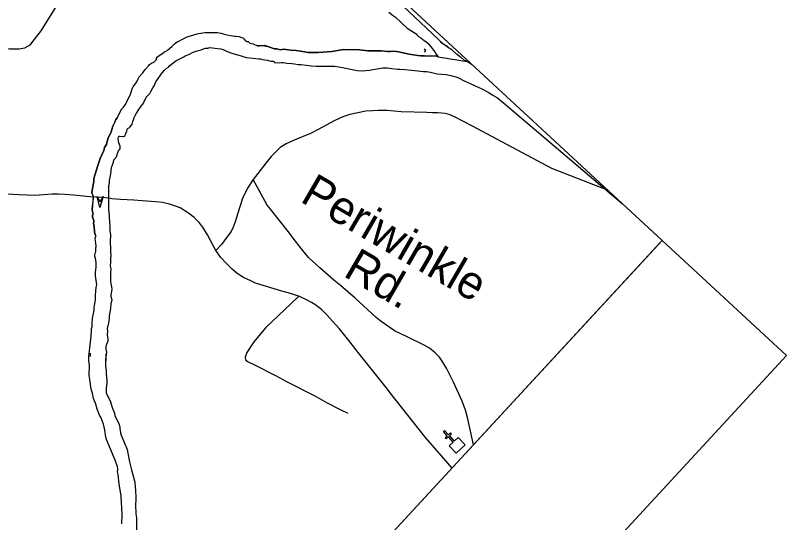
# Model space of a CAD drawing. Extents: x 1766669 to 1770980, y 998119 to 1002502.
# Drawn here: x 1767473.1 to 1767826.5, y 999768 to 1000000.2 of the extents above; entities that cross this region are included whole.
import ezdxf

# ---------------------------------------------------------------- set-up
doc = ezdxf.new("R2010")
doc.units = 0
for name, color, linetype in [('Default', 7, 'Continuous'), ('Default Symbol CELL', 7, 'Continuous'), ('Exist DTM Breakline', 7, 'Continuous'), ('Exist DTM Breakline Underwater', 7, 'Continuous'), ('Exist Roads EOP Other', 7, 'Continuous'), ('Exist Roads EOT', 7, 'Continuous'), ('Exist Structure Minor Paved Ditch or Gutter', 7, 'Continuous'), ('Exist Structure Minor Pipes RCP 24 Inch', 7, 'Continuous')]:
    doc.layers.add(name, color=color, linetype=linetype)

msp = doc.modelspace()

# ---------------------------------------------------------------- linework, layer by layer
at = {"layer": 'Default'}
msp.add_lwpolyline([(1766911.45, 999825.82), (1767342.39, 1000292.03), (1767769.56, 999897.17), (1767338.62, 999430.96)], close=True, dxfattribs=at)
at = {"layer": 'Default Symbol CELL'}
for p, q in [((1767342.36, 1000292.01), (1767826.53, 999844.47)), ((1767768.82, 999896.41), (1767338.6, 999430.98)), ((1767826.53, 999844.47), (1767395.61, 999378.28))]:
    msp.add_line(p, q, dxfattribs=at)
at = {"layer": 'Exist DTM Breakline'}
msp.add_line((1767673.22, 999792.94), (1767668.44, 999798.57), dxfattribs=at)
for points in [[(1767744.52, 999920.27), (1767718.97, 999930.12), (1767682.53, 999949.56), (1767674.38, 999953.84), (1767671.91, 999954.85), (1767670.13, 999955.34), (1767666.77, 999955.68), (1767664.27, 999955.67), (1767661.59, 999955.83), (1767649.9, 999956.09), (1767643.55, 999956.64), (1767639.34, 999956.7), (1767636.75, 999956.49), (1767633.63, 999956.41), (1767626.44, 999954.8), (1767623.18, 999953.73), (1767619.45, 999952.16), (1767611.78, 999947.92), (1767608.37, 999946.17), (1767600.91, 999943.15), (1767597.25, 999941.41), (1767594.43, 999939.8), (1767590.33, 999935.59), (1767587.91, 999932.55), (1767582.1, 999925.03)], [(1767582.1, 999925.03), (1767579.47, 999921.05), (1767577, 999916.04), (1767576.42, 999913.95), (1767575.64, 999911.71), (1767573.83, 999905.78), (1767572.93, 999903.2), (1767572.01, 999901.34), (1767569.96, 999898.67), (1767567.5, 999895.4), (1767565, 999892.58)], [(1767683.03, 999803.6), (1767680.49, 999815.42), (1767679.34, 999819.47), (1767677.87, 999823.57), (1767673.86, 999832.24), (1767670.79, 999838.35), (1767668.97, 999841.51), (1767667.42, 999843.74), (1767665.42, 999845.79), (1767662.85, 999847.84), (1767660.38, 999849.18), (1767652.71, 999853.09), (1767646.85, 999855.81), (1767644.66, 999857.29), (1767640.75, 999860.09), (1767638.38, 999861.96), (1767628.75, 999870.69), (1767622.06, 999876.52), (1767618.98, 999878.95), (1767612.69, 999884.63), (1767607.44, 999889.36), (1767604.86, 999892.56), (1767601.42, 999896.91), (1767597.59, 999901.84), (1767589.94, 999911.55), (1767588.52, 999913.33), (1767582.1, 999925.03)], [(1767512.56, 999916.78), (1767507.18, 999917.1), (1767502.85, 999917.55), (1767499.63, 999917.94), (1767495.74, 999918.17), (1767492.81, 999918.36), (1767489.89, 999918.34), (1767482.03, 999917.75), (1767474.65, 999918.11), (1767466.43, 999918.58), (1767458.13, 999919.31), (1767453.55, 999919.51), (1767447.21, 999920.15), (1767443.86, 999920.35), (1767440.57, 999920.8)], [(1767565, 999892.58), (1767561.12, 999899.82), (1767559.03, 999903.23), (1767557.28, 999905.34), (1767554.98, 999907.66), (1767552.49, 999909.67), (1767548.55, 999912.06), (1767546.41, 999912.95), (1767543.7, 999913.87), (1767540.54, 999914.57), (1767537.3, 999914.87), (1767531.15, 999915.27), (1767527.31, 999915.56), (1767521.19, 999916.01), (1767517.22, 999916.27), (1767516.11, 999916.51), (1767512.56, 999916.78)], [(1767603.06, 999871.72), (1767598.17, 999873.27), (1767595.23, 999874.03), (1767583.06, 999877.69), (1767580.92, 999878.68), (1767577.64, 999880.27), (1767574.78, 999882.03), (1767572.42, 999883.99), (1767569.83, 999886.59), (1767567.25, 999889.4), (1767565, 999892.58)], [(1767603.06, 999871.72), (1767599.34, 999868.17), (1767587.83, 999857.28), (1767582.39, 999850.7), (1767579.2, 999845.85), (1767578.36, 999843.81), (1767578.58, 999842.56), (1767579.75, 999841.63), (1767582.68, 999840.25), (1767592.29, 999835.4), (1767597.31, 999832.59), (1767610.39, 999826.04), (1767615.61, 999823.05), (1767621.87, 999819.79), (1767625.41, 999818.07)], [(1767668.44, 999798.57), (1767661.05, 999807.01), (1767644.88, 999827.47), (1767643.59, 999829.08), (1767630.21, 999845.9), (1767626.54, 999850.67), (1767621.61, 999856.73), (1767618.46, 999860.28), (1767615.82, 999863.13), (1767613.32, 999865.49), (1767610.76, 999867.55), (1767608.77, 999868.83), (1767606.8, 999869.87), (1767603.06, 999871.72)]]:
    msp.add_lwpolyline(points, dxfattribs=at)
at = {"layer": 'Exist DTM Breakline Underwater'}
msp.add_lwpolyline([(1767546.9, 1000094.09), (1767543.97, 1000089.39), (1767543.53, 1000088.68), (1767539.35, 1000082.48), (1767527.82, 1000062.47), (1767521.46, 1000052.31), (1767512.44, 1000038.59), (1767508.74, 1000032.63), (1767496.39, 1000011.99), (1767484.78, 999993.13), (1767480.48, 999987.65), (1767479.64, 999986.62), (1767477.21, 999985.17), (1767474.96, 999984.72), (1767470.32, 999984.72), (1767464.69, 999985.28), (1767456.33, 999986.13), (1767449.03, 999986.62)], dxfattribs=at)
at = {"layer": 'Exist Roads EOP Other'}
msp.add_lwpolyline([(1767513.34, 999917.27), (1767511.8, 999912.26), (1767510.63, 999917.37), (1767511.9, 999914.88)], close=True, dxfattribs=at)
at = {"layer": 'Exist Roads EOT'}
for p, q in [((1767668.65, 999987.39), (1767667.88, 999987.99)), ((1767671.3, 999985.83), (1767668.65, 999987.39)), ((1767661.18, 999984.11), (1767660.41, 999984.84)), ((1767660.56, 999983.46), (1767661.18, 999984.11)), ((1767507.45, 999844.03), (1767507.46, 999845.56)), ((1767514.69, 999842.02), (1767514.72, 999845.29))]:
    msp.add_line(p, q, dxfattribs=at)
for points in [[(1767682.65, 999977.5), (1767681.68, 999978.04), (1767680.07, 999979.11), (1767678.93, 999979.59), (1767677.27, 999981.05), (1767676.73, 999981.33), (1767675.56, 999982.3), (1767675.25, 999982.45), (1767673.06, 999984.48), (1767671.14, 999985.66), (1767670.32, 999986.27), (1767669.51, 999986.93), (1767525.88, 1000122.37)], [(1767644.19, 1000001.69), (1767646.32, 1000000.07), (1767647.25, 999999.47), (1767652.69, 999994.43), (1767656.24, 999992.11), (1767656.71, 999991.73), (1767657.18, 999991.19), (1767657.81, 999990.62), (1767658.93, 999989.99), (1767660.46, 999988.68), (1767661.18, 999988.25), (1767662.39, 999987.16), (1767665.35, 999983.6), (1767665.87, 999982.54), (1767666.83, 999981.22), (1767665.55, 999981.68)], [(1767541.76, 999983.76), (1767542.45, 999984.09), (1767542.79, 999984.27), (1767544.77, 999985.95), (1767545.48, 999986.81), (1767545.97, 999987.23), (1767546.54, 999987.53), (1767547.43, 999988.24), (1767547.95, 999988.44), (1767549.65, 999989.33), (1767551.82, 999990.36), (1767556.45, 999991.85), (1767558.87, 999992.25), (1767560.13, 999992.39), (1767561.36, 999992.44), (1767563.76, 999992.46), (1767565.65, 999992.34), (1767567.37, 999992.06), (1767568.76, 999991.65), (1767571.58, 999991.01), (1767573.72, 999990.79), (1767574.33, 999990.7)], [(1767574.33, 999990.7), (1767575.53, 999990.52), (1767576.73, 999990.19), (1767577.31, 999989.93), (1767577.82, 999989.54), (1767578.55, 999988.64), (1767578.83, 999988.45), (1767579.16, 999988.29), (1767579.71, 999988.24), (1767580.51, 999987.6), (1767582.07, 999987.28), (1767584.02, 999986.36)], [(1767665.55, 999981.68), (1767663.87, 999981.64), (1767660.61, 999981.68), (1767658.96, 999981.73), (1767657.54, 999981.92), (1767653.49, 999982.55), (1767648.74, 999983.56), (1767646.79, 999983.82), (1767644.99, 999983.74), (1767643.63, 999983.77), (1767640.79, 999983.97), (1767638.3, 999983.94), (1767634.67, 999984.09), (1767630.74, 999984.51), (1767623.46, 999984.56), (1767618.05, 999983.77), (1767611.92, 999983.32), (1767607.2, 999983.28), (1767604.62, 999983.74), (1767603.71, 999983.81), (1767601.71, 999984.14), (1767599.37, 999984.36), (1767597.03, 999984.7), (1767595.86, 999984.74), (1767594.9, 999984.54), (1767594.04, 999984.58), (1767592.87, 999984.91), (1767592.4, 999984.86), (1767591.84, 999984.93), (1767588.84, 999986.06), (1767588.38, 999986.17), (1767587.72, 999986.22), (1767587.18, 999986.4), (1767584.84, 999986.3), (1767584.02, 999986.36)], [(1767515.76, 999921.57), (1767515.96, 999922.08), (1767516.13, 999922.83), (1767516.19, 999923.63), (1767516.16, 999924.63), (1767516.87, 999927.68), (1767517.21, 999930.63), (1767517.98, 999933), (1767518.17, 999934.03), (1767519.46, 999935.44), (1767520.19, 999937.85), (1767520.54, 999938.62), (1767520.94, 999939.02), (1767521.13, 999939.48), (1767521.15, 999940.04), (1767521.09, 999940.36), (1767520.87, 999941.14), (1767520.54, 999941.87), (1767520.33, 999942.66), (1767520.24, 999943.91), (1767520.27, 999944.44), (1767520.36, 999944.65), (1767520.57, 999944.89), (1767521.02, 999945), (1767522.12, 999944.74), (1767522.53, 999944.77), (1767522.9, 999944.89), (1767523.38, 999945.3), (1767523.55, 999945.88), (1767524.22, 999947.19), (1767524.35, 999948.08), (1767524.73, 999948.54), (1767525.16, 999948.76), (1767525.53, 999949.07), (1767526.26, 999949.97), (1767526.53, 999950.47), (1767526.87, 999951.66), (1767527.19, 999952.35), (1767527.59, 999953.54), (1767527.96, 999954.33), (1767528.61, 999955.52), (1767528.96, 999955.96), (1767529.34, 999956.67), (1767531.06, 999959.15), (1767531.41, 999959.5), (1767531.88, 999960.18), (1767532.04, 999960.83), (1767532.53, 999961.65), (1767532.96, 999962.75), (1767533.32, 999963.17), (1767534.26, 999963.96), (1767534.66, 999964.49), (1767535.19, 999965.36), (1767536.03, 999967.04), (1767536.62, 999967.94), (1767537.16, 999969.12), (1767537.39, 999969.82), (1767538.27, 999970.83), (1767539.96, 999973.33), (1767541.32, 999975.01), (1767542.19, 999975.9), (1767543.28, 999976.61), (1767543.87, 999977.23), (1767546.59, 999979.49), (1767548.77, 999980.57), (1767550.02, 999981.07), (1767550.97, 999981.67), (1767552.63, 999982.36), (1767554.61, 999983.38), (1767556.38, 999983.99), (1767558.2, 999984.47), (1767559.26, 999984.95), (1767560.15, 999985.16), (1767561.24, 999985.28), (1767562.17, 999985.52), (1767563.37, 999985.46), (1767565.77, 999985.04), (1767567.23, 999984.86)], [(1767519.8, 999953.37), (1767521.94, 999957.44), (1767522.67, 999958.24), (1767523.79, 999959.9), (1767524.07, 999960.56), (1767525.45, 999963.1), (1767525.83, 999964.1), (1767526.56, 999966.64), (1767527.09, 999967.54), (1767528.34, 999969.17), (1767528.89, 999970.13), (1767529.3, 999971.14), (1767529.87, 999972.07), (1767531.51, 999973.91), (1767532.57, 999975.48), (1767534.2, 999977.33), (1767534.6, 999977.71), (1767535.54, 999978.42), (1767536.56, 999978.89), (1767537.07, 999979.24), (1767537.51, 999979.68), (1767537.73, 999980.11), (1767537.75, 999980.62), (1767538.19, 999981.22), (1767538.97, 999981.95), (1767541.12, 999983.21), (1767541.64, 999983.7), (1767541.76, 999983.76)], [(1767567.23, 999984.86), (1767568.6, 999984.44), (1767570.18, 999983.72), (1767572.25, 999982.9), (1767577.08, 999981.56), (1767577.39, 999981.39), (1767578.97, 999981.03), (1767584.75, 999980.32), (1767585.42, 999980.28), (1767586.23, 999980.11), (1767588.67, 999979.81), (1767589.59, 999979.47), (1767590.25, 999979.33), (1767591.24, 999979.35), (1767591.56, 999979.21), (1767591.86, 999978.63), (1767592.09, 999978.53), (1767593.09, 999978.62), (1767594.07, 999978.57), (1767595.19, 999978.69), (1767595.93, 999978.66), (1767597.51, 999978.37), (1767599.72, 999978.29), (1767601.07, 999978.13), (1767602.76, 999977.82), (1767604.09, 999977.75), (1767606.38, 999977.38), (1767608.65, 999977.13), (1767610.86, 999977), (1767616.35, 999976.96), (1767618.05, 999977.03), (1767619.34, 999976.98), (1767621.35, 999976.72), (1767623.78, 999976.3), (1767626.6, 999975.65), (1767629.73, 999975.04), (1767632.03, 999974.88)], [(1767632.03, 999974.88), (1767633.71, 999974.97), (1767635.37, 999975.15), (1767639.63, 999975.93), (1767641.55, 999976.2), (1767642.33, 999976.25), (1767643.42, 999976.21), (1767644.62, 999976.04), (1767645.6, 999975.98), (1767648.19, 999975.64), (1767649.29, 999975.6), (1767651.51, 999975.39), (1767656.19, 999975.03), (1767660.08, 999974.57), (1767661.52, 999974.52), (1767663.27, 999974.26), (1767666.39, 999973.52), (1767670.46, 999973.14), (1767672.7, 999972.77), (1767675, 999972.1), (1767676.22, 999971.59), (1767678.74, 999970.29), (1767681.49, 999969.09), (1767683.8, 999967.95), (1767686.63, 999966.78), (1767690.06, 999964.88), (1767691.59, 999963.89), (1767694, 999962.48), (1767695.3, 999961.41), (1767695.9, 999961.04), (1767696.8, 999960.16), (1767751.38, 999913.93)], [(1767519.8, 999953.37), (1767519.18, 999952.53), (1767518.72, 999951.33), (1767517.72, 999949.57), (1767517.34, 999948.02), (1767516.91, 999946.96), (1767515.42, 999943.76), (1767514.78, 999941.18), (1767513.93, 999939.69), (1767513.74, 999939.07)], [(1767513.74, 999939.07), (1767513.55, 999938.18), (1767512.99, 999937.09), (1767512.66, 999936.17), (1767512.14, 999935.16), (1767510.83, 999931.45), (1767509.11, 999925.51), (1767509.09, 999924.18), (1767508.2, 999920.27), (1767508.06, 999918.87), (1767508.66, 999917.58), (1767508.43, 999913.25)], [(1767515.76, 999921.57), (1767515.76, 999912.76), (1767515.83, 999912.32), (1767515.76, 999911.54), (1767516.05, 999908.28), (1767516.16, 999905.07), (1767516.38, 999903.84), (1767516.44, 999901.43), (1767516.62, 999899.9), (1767516.55, 999896.43), (1767516.71, 999893.53), (1767516.69, 999892.32), (1767516.8, 999890.15), (1767516.67, 999889.12), (1767516.69, 999887.28), (1767516.52, 999885.76), (1767516.72, 999884.84), (1767516.83, 999883.99)], [(1767508.43, 999913.25), (1767508.42, 999912.68), (1767508.29, 999911.65), (1767508.47, 999910.18), (1767508.69, 999909.45), (1767508.45, 999908.67), (1767508.48, 999908.05), (1767509.02, 999906.17), (1767509.04, 999905.7), (1767508.96, 999905.14), (1767509.19, 999903.36), (1767509.36, 999901.08), (1767509.53, 999900.29), (1767509.81, 999899.64)], [(1767509.47, 999889.81), (1767509.48, 999890.42), (1767509.71, 999891.32), (1767509.96, 999891.95), (1767509.96, 999893.37), (1767510.06, 999894.69), (1767510.02, 999895.81), (1767509.72, 999898.28), (1767509.99, 999899.05), (1767509.89, 999899.44), (1767509.81, 999899.64)], [(1767507.1, 999846.74), (1767507.19, 999847.96), (1767507.81, 999853.41), (1767507.94, 999855.91), (1767508.04, 999856.8), (1767508.21, 999857.56), (1767508.31, 999859.04), (1767508.35, 999861.38), (1767508.64, 999862.35), (1767508.9, 999863.68), (1767509.12, 999865.08), (1767509.23, 999866.58), (1767509.76, 999869.77), (1767509.87, 999870.99), (1767509.84, 999872.07), (1767509.96, 999873.91), (1767510.16, 999875.65), (1767510.36, 999876.79), (1767509.8, 999880.94), (1767509.76, 999881.87), (1767509.85, 999882.72), (1767510.07, 999884.92), (1767510.11, 999887.1), (1767509.79, 999889.02), (1767509.47, 999889.81)], [(1767516.83, 999883.99), (1767516.69, 999882.58), (1767516.71, 999878.52), (1767516.85, 999877.37), (1767517.18, 999875.94), (1767517.27, 999874.79), (1767516.77, 999872.23), (1767516.77, 999871.9), (1767516.82, 999871.48), (1767517.13, 999870.63), (1767517.22, 999869.85), (1767516.79, 999868.21), (1767516.63, 999865.97), (1767516.04, 999862.73), (1767516.1, 999861.52), (1767515.89, 999860.41), (1767515.77, 999859.27), (1767515.39, 999858.09), (1767515.17, 999856.94), (1767515.25, 999855.51), (1767515.18, 999854.11), (1767515.52, 999851.98), (1767515.49, 999851.64), (1767515.38, 999851.1), (1767514.69, 999849.16), (1767514.5, 999848.44), (1767514.57, 999847.38), (1767514.79, 999846.05), (1767514.74, 999845.01), (1767514.44, 999842.75), (1767514.34, 999840.84), (1767514.38, 999839.89), (1767514.68, 999837.36), (1767514.72, 999836.13), (1767515.06, 999833.22), (1767514.98, 999831.89), (1767514.63, 999829.68), (1767514.63, 999829.12)], [(1767508.83, 999824.85), (1767508.37, 999827.21), (1767507.86, 999829.03), (1767507.28, 999833.54), (1767507.07, 999834.41), (1767506.95, 999835.31), (1767507.02, 999839.92), (1767506.76, 999842.25), (1767506.73, 999843.19), (1767506.79, 999844.25), (1767507.08, 999846.45), (1767507.1, 999846.74)], [(1767514.63, 999829.12), (1767514.76, 999827.45), (1767516.74, 999823.24), (1767517.47, 999820.67), (1767518.56, 999818.1), (1767518.69, 999817.05), (1767518.94, 999816.26), (1767520.48, 999813.37), (1767520.88, 999811.85), (1767520.9, 999811.1), (1767521.24, 999809.14), (1767521.62, 999807.95), (1767523.36, 999803.52), (1767523.69, 999803), (1767524.24, 999801.48), (1767524.65, 999799.78), (1767525.34, 999795.79), (1767526.23, 999792.16), (1767527.7, 999787.15), (1767527.86, 999786.27), (1767528.14, 999782.7), (1767528.23, 999779.68), (1767528.27, 999778.35), (1767528.11, 999776.21), (1767528.32, 999772.04), (1767528.58, 999770.12), (1767528.61, 999769.15), (1767528.42, 999757.73)], [(1767521.82, 999767.4), (1767521.96, 999771.75), (1767521.57, 999780.07), (1767520.65, 999785.76), (1767520.23, 999789.95), (1767520.02, 999790.67), (1767519.94, 999791.27), (1767519.98, 999792.28), (1767520.08, 999792.61), (1767519.86, 999793.59), (1767518.76, 999796.62), (1767518.28, 999797.56), (1767514.82, 999806.09), (1767514.52, 999807.12), (1767514.34, 999808.23), (1767514.3, 999809.41), (1767513.98, 999811.07), (1767513.5, 999812.99), (1767513.02, 999814.28), (1767512.18, 999816.2), (1767511.65, 999817.1), (1767510.54, 999819.85), (1767509.94, 999822.24), (1767508.83, 999824.85)]]:
    msp.add_lwpolyline(points, dxfattribs=at)
at = {"layer": 'Exist Structure Minor Paved Ditch or Gutter'}
msp.add_lwpolyline([(1767671.94, 999803.17), (1767673.73, 999804.84), (1767671.51, 999807.24), (1767670.5, 999806.31), (1767670.03, 999806.81), (1767671.04, 999807.75), (1767669.28, 999809.64), (1767669.79, 999810.11), (1767671.54, 999808.21), (1767672.55, 999809.15), (1767673.02, 999808.65), (1767672.01, 999807.71), (1767674.24, 999805.31), (1767676.06, 999806.99), (1767679.17, 999803.63), (1767675.05, 999799.81)], close=True, dxfattribs=at)
at = {"layer": 'Exist Structure Minor Pipes RCP 24 Inch'}
msp.add_lwpolyline([(1767521.82, 999767.4), (1767521.96, 999771.75), (1767521.57, 999780.07), (1767520.65, 999785.76), (1767520.23, 999789.95), (1767520.02, 999790.67), (1767519.94, 999791.27), (1767519.98, 999792.28), (1767520.08, 999792.61), (1767519.86, 999793.59), (1767518.76, 999796.62), (1767518.28, 999797.56), (1767514.82, 999806.09), (1767514.52, 999807.12), (1767514.34, 999808.23), (1767514.3, 999809.41), (1767513.98, 999811.07), (1767513.5, 999812.99), (1767513.02, 999814.28), (1767512.18, 999816.2), (1767511.65, 999817.1), (1767510.54, 999819.85), (1767509.94, 999822.24), (1767508.83, 999824.85), (1767508.37, 999827.21), (1767507.86, 999829.03), (1767507.28, 999833.54), (1767507.07, 999834.41), (1767506.95, 999835.31), (1767507.02, 999839.92), (1767506.76, 999842.25), (1767506.73, 999843.19), (1767506.79, 999844.25), (1767507.08, 999846.45), (1767507.1, 999846.74), (1767507.19, 999847.96), (1767507.81, 999853.41), (1767507.94, 999855.91), (1767508.04, 999856.8), (1767508.21, 999857.56), (1767508.31, 999859.04), (1767508.35, 999861.38), (1767508.64, 999862.35), (1767508.9, 999863.68), (1767509.12, 999865.08), (1767509.23, 999866.58), (1767509.76, 999869.77), (1767509.87, 999870.99), (1767509.84, 999872.07), (1767509.96, 999873.91), (1767510.16, 999875.65), (1767510.36, 999876.79), (1767509.8, 999880.94), (1767509.76, 999881.87), (1767509.85, 999882.72), (1767510.07, 999884.92), (1767510.11, 999887.1), (1767509.79, 999889.02), (1767509.47, 999889.81), (1767509.48, 999890.42), (1767509.71, 999891.32), (1767509.96, 999891.95), (1767509.96, 999893.37), (1767510.06, 999894.69), (1767510.02, 999895.81), (1767509.72, 999898.28), (1767509.99, 999899.05), (1767509.89, 999899.44), (1767509.81, 999899.64), (1767509.53, 999900.29), (1767509.36, 999901.08), (1767509.19, 999903.36), (1767508.96, 999905.14), (1767509.04, 999905.7), (1767509.02, 999906.17), (1767508.48, 999908.05), (1767508.45, 999908.67), (1767508.69, 999909.45), (1767508.47, 999910.18), (1767508.29, 999911.65), (1767508.42, 999912.68), (1767508.43, 999913.25), (1767508.51, 999913.92), (1767508.91, 999916.48), (1767508.66, 999917.58), (1767508.06, 999918.87), (1767508.2, 999920.27), (1767509.09, 999924.18), (1767509.11, 999925.51), (1767510.83, 999931.45), (1767512.14, 999935.16), (1767512.66, 999936.17), (1767512.99, 999937.09), (1767513.55, 999938.18), (1767513.74, 999939.07), (1767513.93, 999939.69), (1767514.78, 999941.18), (1767515.42, 999943.76), (1767516.91, 999946.96), (1767517.34, 999948.02), (1767517.72, 999949.57), (1767518.72, 999951.33), (1767519.18, 999952.53), (1767519.8, 999953.37), (1767521.94, 999957.44), (1767522.67, 999958.24), (1767523.79, 999959.9), (1767524.07, 999960.56), (1767525.45, 999963.1), (1767525.83, 999964.1), (1767526.56, 999966.64), (1767527.09, 999967.54), (1767528.34, 999969.17), (1767528.89, 999970.13), (1767529.3, 999971.14), (1767529.87, 999972.07), (1767531.51, 999973.91), (1767532.57, 999975.48), (1767534.2, 999977.33), (1767534.6, 999977.71), (1767535.54, 999978.42), (1767536.56, 999978.89), (1767537.07, 999979.24), (1767537.51, 999979.68), (1767537.73, 999980.11), (1767537.75, 999980.62), (1767538.19, 999981.22), (1767538.97, 999981.95), (1767541.12, 999983.21), (1767541.64, 999983.7), (1767541.76, 999983.76), (1767542.45, 999984.09), (1767542.79, 999984.27), (1767544.77, 999985.95), (1767545.48, 999986.81), (1767545.97, 999987.23), (1767546.54, 999987.53), (1767547.43, 999988.24), (1767547.95, 999988.44), (1767549.65, 999989.33), (1767551.83, 999990.36), (1767556.45, 999991.85), (1767558.87, 999992.25), (1767560.13, 999992.39), (1767561.36, 999992.44), (1767563.76, 999992.46), (1767565.65, 999992.34), (1767567.37, 999992.06), (1767568.76, 999991.65), (1767571.58, 999991.01), (1767573.72, 999990.79), (1767574.33, 999990.7), (1767575.53, 999990.52), (1767576.73, 999990.19), (1767577.31, 999989.93), (1767577.82, 999989.54), (1767578.55, 999988.64), (1767578.83, 999988.45), (1767579.16, 999988.29), (1767579.71, 999988.24), (1767580.52, 999987.6), (1767582.07, 999987.28), (1767584.02, 999986.36), (1767584.84, 999986.3), (1767587.18, 999986.4), (1767587.72, 999986.22), (1767588.38, 999986.17), (1767588.84, 999986.06), (1767591.84, 999984.93), (1767592.4, 999984.86), (1767592.87, 999984.91), (1767594.04, 999984.58), (1767594.9, 999984.54), (1767595.86, 999984.74), (1767597.03, 999984.7), (1767599.37, 999984.36), (1767601.71, 999984.14), (1767603.71, 999983.81), (1767604.62, 999983.74), (1767607.2, 999983.28), (1767611.92, 999983.32), (1767618.05, 999983.77), (1767623.46, 999984.56), (1767630.74, 999984.51), (1767634.67, 999984.09), (1767638.3, 999983.94), (1767640.79, 999983.97), (1767643.63, 999983.77), (1767644.99, 999983.74), (1767646.79, 999983.82), (1767648.74, 999983.56), (1767653.49, 999982.55), (1767657.54, 999981.92), (1767658.96, 999981.73), (1767660.61, 999981.68), (1767663.87, 999981.64), (1767665.55, 999981.68), (1767666.83, 999981.22), (1767681.09, 999978.95)], dxfattribs=at)

# ---------------------------------------------------------------- texts
at = {"layer": 'Default Symbol CELL'}
for s, p in [('Periwinkle', (1767603.06, 999915.24)), (' Rd.', (1767617.94, 999883.97))]:
    msp.add_text(s, height=15.235, rotation=329.8554, dxfattribs=at).set_placement(p)

doc.saveas('drawing.dxf')
